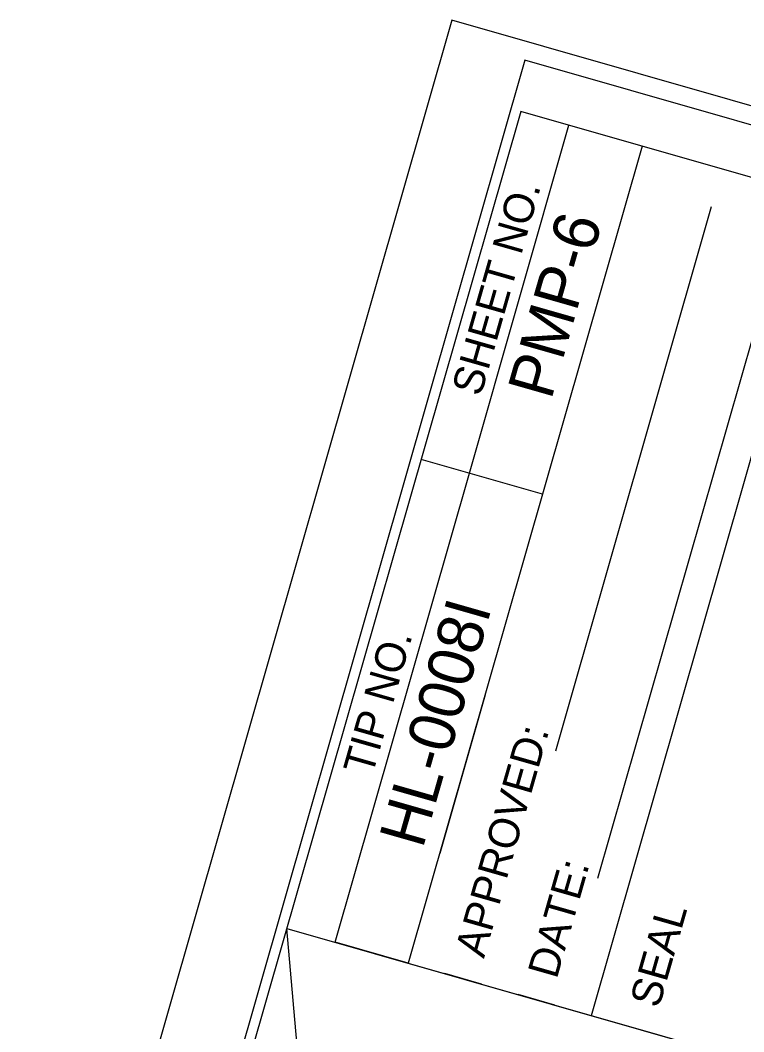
# Model space of a CAD drawing. Extents: x 2096990 to 2098506, y 687712 to 690186.
# Drawn here: x 2097347.2 to 2097525.6, y 689382.1 to 689631.6 of the extents above; entities that cross this region are included whole.
import ezdxf

# ---------------------------------------------------------------- set-up
doc = ezdxf.new("R2010")
doc.units = 0
for name, color, linetype in [('Sheet Data Field CELL', 7, 'Continuous'), ('Sheet Layout Plan Border', 7, 'Continuous'), ('Sheet Plan CELL', 7, 'Continuous'), ('Sheet Plot Border Inside CELL', 7, 'Continuous'), ('Sheet Plot Border Outside CELL', 7, 'Continuous'), ('Sheet Title CELL', 7, 'Continuous')]:
    doc.layers.add(name, color=color, linetype=linetype)

msp = doc.modelspace()

# ---------------------------------------------------------------- linework, layer by layer
at = {"layer": 'Sheet Layout Plan Border'}
msp.add_lwpolyline([(2098367.95, 688928.37), (2098117.8, 688054.49), (2097561.27, 688075.84), (2097494.46, 688123.79), (2097678.88, 688820.99), (2097441.61, 689082.36), (2097412.96, 689407.62), (2097643.79, 689341.54), (2097686.55, 689490.94), (2097794.81, 689516.31), (2097855.09, 689499.05), (2097840.29, 689446.58), (2098381.23, 689292.72), (2098283.83, 688952.45)], close=True, dxfattribs=at)
at = {"layer": 'Sheet Plan CELL'}
for p, q in [((2097470.64, 689609.1), (2097057.83, 688167.01)), ((2098480.09, 689320.14), (2097470.64, 689609.1))]:
    msp.add_line(p, q, dxfattribs=at)
at = {"layer": 'Sheet Plot Border Inside CELL'}
msp.add_lwpolyline([(2098027.46, 687729.8), (2098485.92, 689331.42), (2097471.68, 689621.77), (2097013.2, 688020.14)], close=True, dxfattribs=at)
at = {"layer": 'Sheet Plot Border Outside CELL'}
msp.add_lwpolyline([(2098043.11, 687711.8), (2098506.41, 689330.25), (2097453.69, 689631.6), (2096990.4, 688013.14)], close=True, dxfattribs=at)
at = {"layer": 'Sheet Title CELL'}
for p, q in [((2097457.98, 689519.88), (2097482.55, 689605.69)), ((2097500.6, 689600.53), (2097442.92, 689399.04)), ((2097488.06, 689386.12), (2097545.74, 689587.61)), ((2097479.28, 689451.37), (2097517.71, 689585.64)), ((2097489.7, 689420.02), (2097535.64, 689580.51)), ((2097476.04, 689514.71), (2097446.07, 689523.29)), ((2097424.87, 689404.21), (2097457.98, 689519.88)), ((2097461.88, 689465.22), (2097450.69, 689426.12)), ((2097412.96, 689407.62), (2097594.87, 689355.54)), ((2097442.92, 689399.04), (2097424.87, 689404.21)), ((2097460.99, 689393.87), (2097451.96, 689396.45)), ((2097479.03, 689388.7), (2097470.01, 689391.29))]:
    msp.add_line(p, q, dxfattribs=at)

# ---------------------------------------------------------------- texts
at = {"layer": 'Sheet Data Field CELL'}
for s, height, p in [('SHEET NO.', 7.512, (2097460.76, 689538.59)), ('PMP-6', 11.268, (2097478.14, 689537.73)), ('HL-0008I', 11.268, (2097446.46, 689427.05)), ('TIP NO.', 7.512, (2097434.02, 689445.02)), ('APPROVED:', 7.512, (2097461.57, 689400.04)), ('DATE:', 7.512, (2097479.5, 689394.9)), ('SEAL', 7.512, (2097504.7, 689387.69))]:
    msp.add_text(s, height=height, rotation=74.0259, dxfattribs=at).set_placement(p)

doc.saveas('drawing.dxf')
